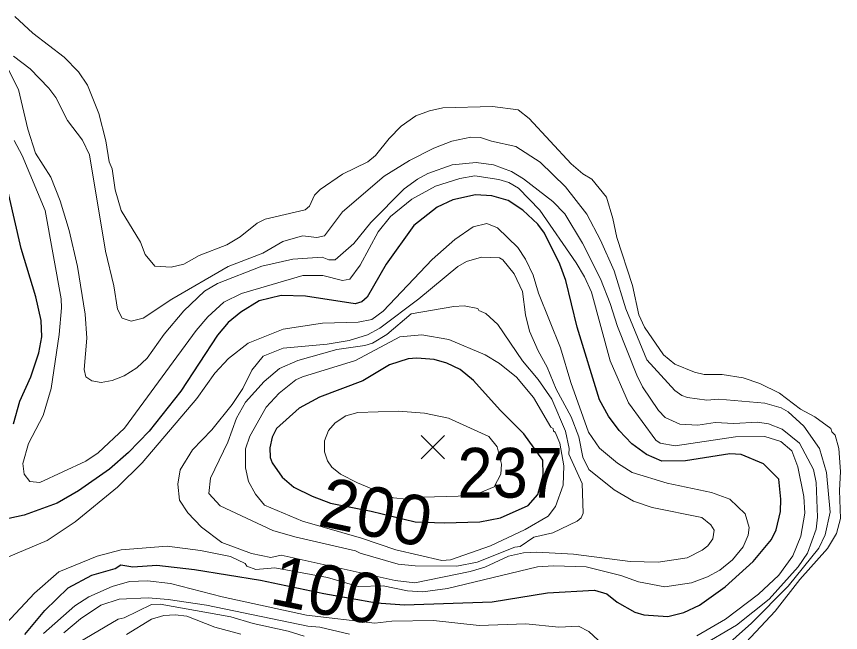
# Model space of a CAD drawing. Extents: x 474.5 to 500, y 7345.7 to 7373.4.
# Drawn here: x 475.818 to 477.141, y 7356.191 to 7357.181 of the extents above; entities that cross this region are included whole.
import ezdxf
from ezdxf.enums import TextEntityAlignment as Align

# ---------------------------------------------------------------- set-up
doc = ezdxf.new("R2010")
doc.units = 0
doc.header["$LTSCALE"] = 0.032
for name, color, linetype, lineweight in [('1', 7, 'Continuous', 25), ('2', 7, 'Continuous', 13), ('21', 7, 'Continuous', 25)]:
    doc.layers.add(name, color=color, linetype=linetype, lineweight=lineweight)
doc.layers.add('61', color=7, linetype='Continuous')

msp = doc.modelspace()

# ---------------------------------------------------------------- linework, layer by layer
at = {"layer": '1'}
for points in [[(475.813, 7356.5263), (475.8235, 7356.5626), (475.8407, 7356.602), (475.8536, 7356.6406), (475.8584, 7356.6662), (475.8575, 7356.6927), (475.8488, 7356.7306), (475.8254, 7356.8079), (475.7963, 7356.9343)], [(475.8315, 7356.1881), (475.8634, 7356.2264), (475.9009, 7356.2631), (475.9389, 7356.283), (475.9765, 7356.294), (475.9854, 7356.3001), (476.0049, 7356.2964), (476.0433, 7356.2994), (476.1038, 7356.2924), (476.2098, 7356.2754), (476.3113, 7356.2537), (476.3961, 7356.2386), (476.4408, 7356.2356), (476.5819, 7356.2405), (476.6705, 7356.2548), (476.746, 7356.2589), (476.7662, 7356.2532), (476.7828, 7356.2398), (476.8112, 7356.2237), (476.8256, 7356.2197), (476.8639, 7356.2166), (476.8897, 7356.2232), (476.9147, 7356.235), (476.9563, 7356.2646), (477.0009, 7356.3051), (477.0305, 7356.3405), (477.0382, 7356.3559), (477.0447, 7356.3854), (477.0456, 7356.4055), (477.0423, 7356.4374), (477.0175, 7356.4622), (476.9817, 7356.4774), (476.9635, 7356.4783), (476.8921, 7356.467), (476.8543, 7356.4662), (476.8299, 7356.4771), (476.806, 7356.4943), (476.7858, 7356.5159), (476.7689, 7356.5386), (476.754, 7356.5648), (476.7181, 7356.6819), (476.7002, 7356.7568), (476.6904, 7356.7832), (476.6659, 7356.833), (476.6551, 7356.847), (476.6312, 7356.8695), (476.6073, 7356.8855), (476.5815, 7356.893), (476.5551, 7356.8946), (476.5185, 7356.8862), (476.4937, 7356.8747), (476.4561, 7356.8453), (476.4117, 7356.7832)], [(476.4117, 7356.7832), (476.3811, 7356.7298), (476.3727, 7356.7227), (476.3619, 7356.7192), (476.2819, 7356.7318), (476.2427, 7356.7326), (476.2078, 7356.7239), (476.178, 7356.7056), (476.1578, 7356.689), (476.1408, 7356.669), (476.082, 7356.579), (476.0311, 7356.5144), (475.998, 7356.4805), (475.9672, 7356.4538), (475.9177, 7356.4189), (475.883, 7356.3987), (475.8302, 7356.3797), (475.7806, 7356.369)]]:
    msp.add_lwpolyline(points, dxfattribs=at)
msp.add_lwpolyline([(476.3047, 7356.5691), (476.2717, 7356.5515), (476.2355, 7356.519), (476.2284, 7356.5049), (476.2247, 7356.488), (476.2254, 7356.4725), (476.2284, 7356.4636), (476.2443, 7356.4409), (476.2633, 7356.4249), (476.2928, 7356.4101), (476.3223, 7356.3991), (476.3874, 7356.3863), (476.4584, 7356.3691), (476.5047, 7356.3672), (476.5618, 7356.3689), (476.595, 7356.3754), (476.6394, 7356.3953), (476.6552, 7356.413), (476.6637, 7356.4444), (476.6631, 7356.4681), (476.6326, 7356.5106), (476.5947, 7356.5483), (476.5519, 7356.5961), (476.5307, 7356.6135), (476.5089, 7356.624), (476.4887, 7356.6297), (476.4611, 7356.6321), (476.4468, 7356.6307), (476.4169, 7356.621), (476.3741, 7356.5956)], close=True, dxfattribs=at)
at = {"layer": '2'}
for points in [[(477.126, 7356.5188), (477.1, 7356.5379), (477.0772, 7356.5502), (477.0434, 7356.5759), (477.0118, 7356.5912), (476.9852, 7356.6002), (476.9512, 7356.6059), (476.9221, 7356.6059), (476.9067, 7356.6095), (476.8751, 7356.6225), (476.8569, 7356.6374), (476.8267, 7356.6815), (476.8172, 7356.7018), (476.8072, 7356.7489), (476.7823, 7356.8258), (476.7758, 7356.8566), (476.7652, 7356.8904), (476.7421, 7356.9194), (476.7274, 7356.9279), (476.7086, 7356.944), (476.6412, 7357.0173), (476.6235, 7357.031), (476.5823, 7357.0366), (476.5028, 7357.0342), (476.4813, 7357.0296), (476.4593, 7357.0211), (476.4358, 7357.0045), (476.4163, 7356.9849), (476.3942, 7356.9574), (476.382, 7356.9472), (476.3413, 7356.9277), (476.3057, 7356.903), (476.2963, 7356.8936), (476.2882, 7356.8761), (476.2814, 7356.8701), (476.2174, 7356.8555), (476.2046, 7356.8489), (476.1773, 7356.8267), (476.1558, 7356.8143), (476.1115, 7356.797), (476.0866, 7356.7831), (476.0664, 7356.7782), (476.0401, 7356.78), (476.0246, 7356.7987), (476.0171, 7356.8183), (475.986, 7356.8694), (475.9765, 7356.9026), (475.9716, 7356.9364), (475.9669, 7356.9475), (475.9612, 7356.9814), (475.9503, 7357.0252), (475.9317, 7357.0704), (475.9177, 7357.0922), (475.8946, 7357.1155), (475.8443, 7357.1541), (475.8152, 7357.181)], [(475.8128, 7357.1174), (475.8398, 7357.0968), (475.87, 7357.0658), (475.8813, 7357.0507), (475.8997, 7357.0139), (475.9238, 7356.9824), (475.935, 7356.9587), (475.961, 7356.8041), (475.9741, 7356.7481), (475.9803, 7356.7105), (475.9875, 7356.6964), (476.0023, 7356.6914), (476.0214, 7356.6964), (476.0672, 7356.727), (476.1577, 7356.7793), (476.2135, 7356.8009), (476.2454, 7356.8192), (476.2771, 7356.8285), (476.3002, 7356.8261), (476.3124, 7356.8284), (476.3413, 7356.8669), (476.4083, 7356.9243), (476.4488, 7356.9496), (476.4879, 7356.9696), (476.5169, 7356.9809), (476.5475, 7356.9871), (476.5633, 7356.9864), (476.5805, 7356.9806), (476.6198, 7356.9719), (476.659, 7356.9468), (476.6995, 7356.9072), (476.7336, 7356.8635), (476.7558, 7356.8215), (476.7778, 7356.7725), (476.7963, 7356.7111), (476.8301, 7356.6292), (476.875, 7356.5801), (476.8862, 7356.5719), (476.8954, 7356.5685), (476.9265, 7356.5644), (476.9456, 7356.5659), (477.0195, 7356.5596), (477.0462, 7356.552), (477.0572, 7356.5456), (477.0824, 7356.5226), (477.1073, 7356.4869), (477.1189, 7356.4482), (477.1245, 7356.3843), (477.1164, 7356.3482)], [(476.9161, 7356.1685), (476.9741, 7356.2028), (477.0265, 7356.2446), (477.0733, 7356.2969), (477.0885, 7356.3184), (477.1022, 7356.3572), (477.1045, 7356.3767), (477.1023, 7356.432), (477.0979, 7356.4532), (477.0754, 7356.4952), (477.0476, 7356.5178), (477.0258, 7356.5262), (477.0078, 7356.5292), (476.9699, 7356.5269), (476.9402, 7356.5284), (476.9121, 7356.5245), (476.883, 7356.526), (476.8595, 7356.5367), (476.8492, 7356.5476), (476.8235, 7356.5858), (476.814, 7356.6044), (476.7829, 7356.6827), (476.7715, 7356.7198), (476.7558, 7356.7593), (476.7271, 7356.8167), (476.6987, 7356.8641), (476.6791, 7356.8836), (476.632, 7356.9203), (476.6129, 7356.9318), (476.5842, 7356.9426), (476.5563, 7356.9464), (476.5177, 7356.9426), (476.4786, 7356.9287), (476.4621, 7356.9198), (476.4406, 7356.904), (476.3867, 7356.8501), (476.3594, 7356.8164), (476.3297, 7356.7897), (476.3193, 7356.7902), (476.3089, 7356.7941), (476.2616, 7356.7908), (476.212, 7356.7798), (476.1406, 7356.7517), (476.1197, 7356.7394), (476.0868, 7356.7081), (476.0549, 7356.6706), (476.0278, 7356.6318), (476.0112, 7356.6163), (475.9909, 7356.6034), (475.9717, 7356.5962), (475.9536, 7356.5931), (475.9389, 7356.5956), (475.9295, 7356.6019), (475.9267, 7356.6138), (475.931, 7356.6643), (475.9279, 7356.7029), (475.916, 7356.7795), (475.9024, 7356.837), (475.888, 7356.8848), (475.8731, 7356.9228), (475.8482, 7356.9616), (475.8362, 7356.9997), (475.821, 7357.0635), (475.8004, 7357.105)], [(475.814, 7356.9818), (475.8271, 7356.9574), (475.864, 7356.8691), (475.8895, 7356.7274), (475.8904, 7356.7126), (475.8864, 7356.6699), (475.8736, 7356.5833), (475.8605, 7356.54), (475.8373, 7356.4949), (475.8282, 7356.4627), (475.8301, 7356.4458), (475.8392, 7356.4337), (475.8552, 7356.432), (475.9295, 7356.4667), (475.9492, 7356.4797), (475.9913, 7356.5192), (476.1062, 7356.6764), (476.1251, 7356.6985), (476.1509, 7356.7219), (476.1794, 7356.7359), (476.278, 7356.7646), (476.3098, 7356.7647), (476.3417, 7356.7567), (476.3532, 7356.7587), (476.3699, 7356.7816), (476.3985, 7356.8351), (476.4185, 7356.8596), (476.4526, 7356.8873), (476.4908, 7356.9084), (476.5299, 7356.9209), (476.5541, 7356.9249), (476.5927, 7356.9193), (476.6086, 7356.9144), (476.6243, 7356.905), (476.6582, 7356.8695), (476.7168, 7356.7853), (476.7303, 7356.7625), (476.7411, 7356.7378), (476.7712, 7356.6279), (476.801, 7356.5604), (476.8448, 7356.5001), (476.8519, 7356.4954), (476.8755, 7356.491), (476.9724, 7356.5054), (477.0198, 7356.5062)], [(475.7702, 7356.2985), (475.8673, 7356.3391), (475.9119, 7356.3687), (475.9799, 7356.4249), (476.0198, 7356.464), (476.1077, 7356.5672), (476.1364, 7356.6079), (476.1583, 7356.6312), (476.1901, 7356.656), (476.2464, 7356.6785), (476.3095, 7356.688), (476.3664, 7356.6897), (476.3884, 7356.6942), (476.4067, 7356.7073), (476.4856, 7356.7903), (476.522, 7356.8226), (476.5511, 7356.8428), (476.5735, 7356.8482), (476.5903, 7356.8414), (476.6229, 7356.8098), (476.6353, 7356.7912), (476.6475, 7356.7652), (476.6562, 7356.7366), (476.6914, 7356.6487), (476.7081, 7356.5928), (476.7363, 7356.5128), (476.754, 7356.4874), (476.7831, 7356.4634), (476.8067, 7356.4484), (476.8629, 7356.4309), (476.9341, 7356.4159), (476.9633, 7356.4056), (476.9879, 7356.3818), (476.9944, 7356.3596), (476.9928, 7356.3474), (476.9852, 7356.3287), (476.9677, 7356.3078), (476.9477, 7356.2915), (476.9279, 7356.2806), (476.9022, 7356.2708), (476.8594, 7356.2644), (476.8167, 7356.2728), (476.7884, 7356.2828), (476.7326, 7356.2964), (476.6805, 7356.298), (476.6549, 7356.2964), (476.5099, 7356.2621), (476.4703, 7356.2565), (476.4457, 7356.2581), (476.4068, 7356.2662), (476.3668, 7356.2653), (476.3176, 7356.2795), (476.2329, 7356.2952), (476.2021, 7356.2923), (476.1877, 7356.2977), (476.1853, 7356.3018), (476.1618, 7356.3132), (476.1134, 7356.3227), (476.0598, 7356.3298), (475.9861, 7356.3242), (475.9476, 7356.314), (475.8861, 7356.2884), (475.847, 7356.2546), (475.8012, 7356.2055)], [(476.9819, 7356.1672), (477.0363, 7356.2256), (477.0759, 7356.2763), (477.1203, 7356.3259), (477.1348, 7356.3502), (477.1412, 7356.3743), (477.1396, 7356.4191), (477.1413, 7356.4501), (477.1387, 7356.4867), (477.1325, 7356.5082), (477.1273, 7356.5138), (477.126, 7356.5188)], [(477.0198, 7356.5062), (477.0453, 7356.4982), (477.063, 7356.483), (477.0727, 7356.4572), (477.0822, 7356.4099), (477.0839, 7356.3829), (477.0775, 7356.346), (477.0649, 7356.3143), (477.0422, 7356.2835), (477.0098, 7356.2526), (476.9567, 7356.2124), (476.9108, 7356.1859)], [(477.1164, 7356.3482), (477.1065, 7356.3266), (477.0573, 7356.2658), (476.9982, 7356.2061), (476.9244, 7356.1404)], [(476.7595, 7356.1716), (476.7373, 7356.1928), (476.7203, 7356.2015), (476.6888, 7356.1998), (476.6359, 7356.2052), (476.5612, 7356.2022), (476.4876, 7356.2102), (476.4205, 7356.2094), (476.3936, 7356.2062), (476.2837, 7356.2188), (476.1482, 7356.2484), (476.0653, 7356.27), (476.0282, 7356.2739), (475.9992, 7356.2731), (475.9714, 7356.2653), (475.9339, 7356.2487), (475.9113, 7356.2342), (475.861, 7356.1896)], [(475.894, 7356.1907), (475.9207, 7356.2133), (475.9534, 7356.2348), (475.9828, 7356.2446), (476.0295, 7356.2468), (476.0614, 7356.2444), (476.1231, 7356.2349), (476.2858, 7356.2014), (476.305, 7356.1998), (476.3525, 7356.1887)], [(476.28, 7356.1851), (476.2544, 7356.1935), (476.1979, 7356.2055), (476.1621, 7356.2164), (476.0485, 7356.2368), (476.0349, 7356.2361), (475.9908, 7356.2148), (475.9813, 7356.2125), (475.9183, 7356.1758)], [(475.9946, 7356.1877), (476.0345, 7356.2124), (476.0546, 7356.2183), (476.0728, 7356.2197), (476.0917, 7356.2173), (476.1364, 7356.1996), (476.1782, 7356.1883)]]:
    msp.add_lwpolyline(points, dxfattribs=at)
for points in [[(476.4642, 7356.7274), (476.5266, 7356.7793), (476.5408, 7356.7875), (476.5647, 7356.7941), (476.5937, 7356.7933), (476.5987, 7356.7902), (476.617, 7356.7672), (476.6303, 7356.7392), (476.6351, 7356.7014), (476.642, 7356.6751), (476.6555, 7356.6439), (476.6704, 7356.6173), (476.6846, 7356.5824), (476.7087, 7356.5375), (476.7208, 7356.5053), (476.7274, 7356.4729), (476.737, 7356.4533), (476.7778, 7356.4206), (476.8088, 7356.4021), (476.839, 7356.3918), (476.9183, 7356.3758), (476.9332, 7356.3639), (476.9385, 7356.3553), (476.9361, 7356.3415), (476.9281, 7356.3305), (476.9192, 7356.3233), (476.895, 7356.3113), (476.8485, 7356.3043), (476.8034, 7356.3054), (476.7123, 7356.317), (476.6535, 7356.3203), (476.6321, 7356.3194), (476.6083, 7356.3138), (476.5698, 7356.2963), (476.5464, 7356.2892), (476.4574, 7356.2708), (476.4262, 7356.2748), (476.2427, 7356.3154), (476.2261, 7356.3116), (476.1952, 7356.3179), (476.1479, 7356.3359), (476.115, 7356.3606), (476.0929, 7356.3835), (476.0799, 7356.404), (476.0771, 7356.4296), (476.081, 7356.4524), (476.1008, 7356.4844), (476.1317, 7356.517), (476.1642, 7356.5573), (476.1814, 7356.5833), (476.1961, 7356.6125), (476.214, 7356.635), (476.2464, 7356.6481), (476.3169, 7356.6546), (476.3521, 7356.6606), (476.3816, 7356.6695), (476.4012, 7356.68)], [(476.4518, 7356.7034), (476.5204, 7356.7151), (476.5371, 7356.7159), (476.559, 7356.7117), (476.5606, 7356.7088), (476.5719, 7356.7037), (476.5907, 7356.6858), (476.6308, 7356.6275), (476.6556, 7356.5976), (476.6776, 7356.5662), (476.6994, 7356.5147), (476.7055, 7356.4866), (476.705, 7356.4775), (476.7264, 7356.4306), (476.7281, 7356.383), (476.7246, 7356.3753), (476.7185, 7356.3698), (476.6791, 7356.3513), (476.6485, 7356.3442), (476.6267, 7356.3292), (476.618, 7356.3282), (476.5576, 7356.3044), (476.5251, 7356.2979), (476.4581, 7356.298), (476.4306, 7356.3008), (476.3698, 7356.3184), (476.3626, 7356.3226), (476.2647, 7356.3446), (476.2294, 7356.3551), (476.1448, 7356.3948), (476.1266, 7356.4146), (476.1295, 7356.4391), (476.1574, 7356.4968), (476.171, 7356.5354), (476.1857, 7356.5613), (476.2157, 7356.5945), (476.2404, 7356.6153), (476.2698, 7356.6283), (476.3321, 7356.6457), (476.3775, 7356.6522), (476.3895, 7356.656), (476.4128, 7356.6701)], [(476.6969, 7356.4592), (476.6903, 7356.4953), (476.6831, 7356.5129), (476.6802, 7356.5144), (476.6799, 7356.5189), (476.6762, 7356.5213), (476.6484, 7356.5689), (476.6208, 7356.6014), (476.5938, 7356.6236), (476.5706, 7356.6374), (476.5124, 7356.6617), (476.469, 7356.6696), (476.4338, 7356.6662), (476.3624, 7356.628), (476.2771, 7356.602), (476.2667, 7356.5969), (476.2395, 7356.5759), (476.2191, 7356.5532), (476.1926, 7356.5068), (476.1856, 7356.4861), (476.1856, 7356.4556), (476.1903, 7356.4338), (476.2015, 7356.4136), (476.2162, 7356.396), (476.2774, 7356.3699), (476.3721, 7356.3427), (476.4272, 7356.324), (476.5012, 7356.307), (476.515, 7356.3081), (476.5791, 7356.3304), (476.6349, 7356.3567), (476.6715, 7356.3778), (476.6838, 7356.3935), (476.6961, 7356.4279)], [(476.3662, 7356.5444), (476.3469, 7356.5393), (476.3295, 7356.5281), (476.3192, 7356.5158), (476.3124, 7356.4992), (476.3127, 7356.4817), (476.3173, 7356.4668), (476.3245, 7356.4567), (476.3385, 7356.4457), (476.3655, 7356.4315), (476.4235, 7356.4075), (476.4444, 7356.4052), (476.4706, 7356.4084), (476.5271, 7356.4102), (476.5621, 7356.4155), (476.5849, 7356.4252), (476.5956, 7356.4456), (476.5966, 7356.4618), (476.59, 7356.4896), (476.5763, 7356.506), (476.5116, 7356.5354), (476.473, 7356.5436), (476.4316, 7356.5469)]]:
    msp.add_lwpolyline(points, close=True, dxfattribs=at)
at = {"layer": '21'}
for p, q in [((476.4679, 7356.5079), (476.5054, 7356.4704)), ((476.5054, 7356.5079), (476.4679, 7356.4704))]:
    msp.add_line(p, q, dxfattribs=at)

# ---------------------------------------------------------------- texts
at = {"layer": '61', "width": 0.95}
msp.add_text('237', height=0.08, dxfattribs=at).set_placement((476.6108, 7356.4078), align=Align.CENTER)
at = {"layer": '61'}
for s, rotation, p in [('200', 348.381, (476.3874, 7356.3454)), ('100', 348.518, (476.3097, 7356.2201))]:
    msp.add_text(s, height=0.08, rotation=rotation, dxfattribs=at).set_placement(p, align=Align.CENTER)

doc.saveas('drawing.dxf')
